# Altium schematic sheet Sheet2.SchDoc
size A3; SheetNumber: 2; SheetTotal: 2
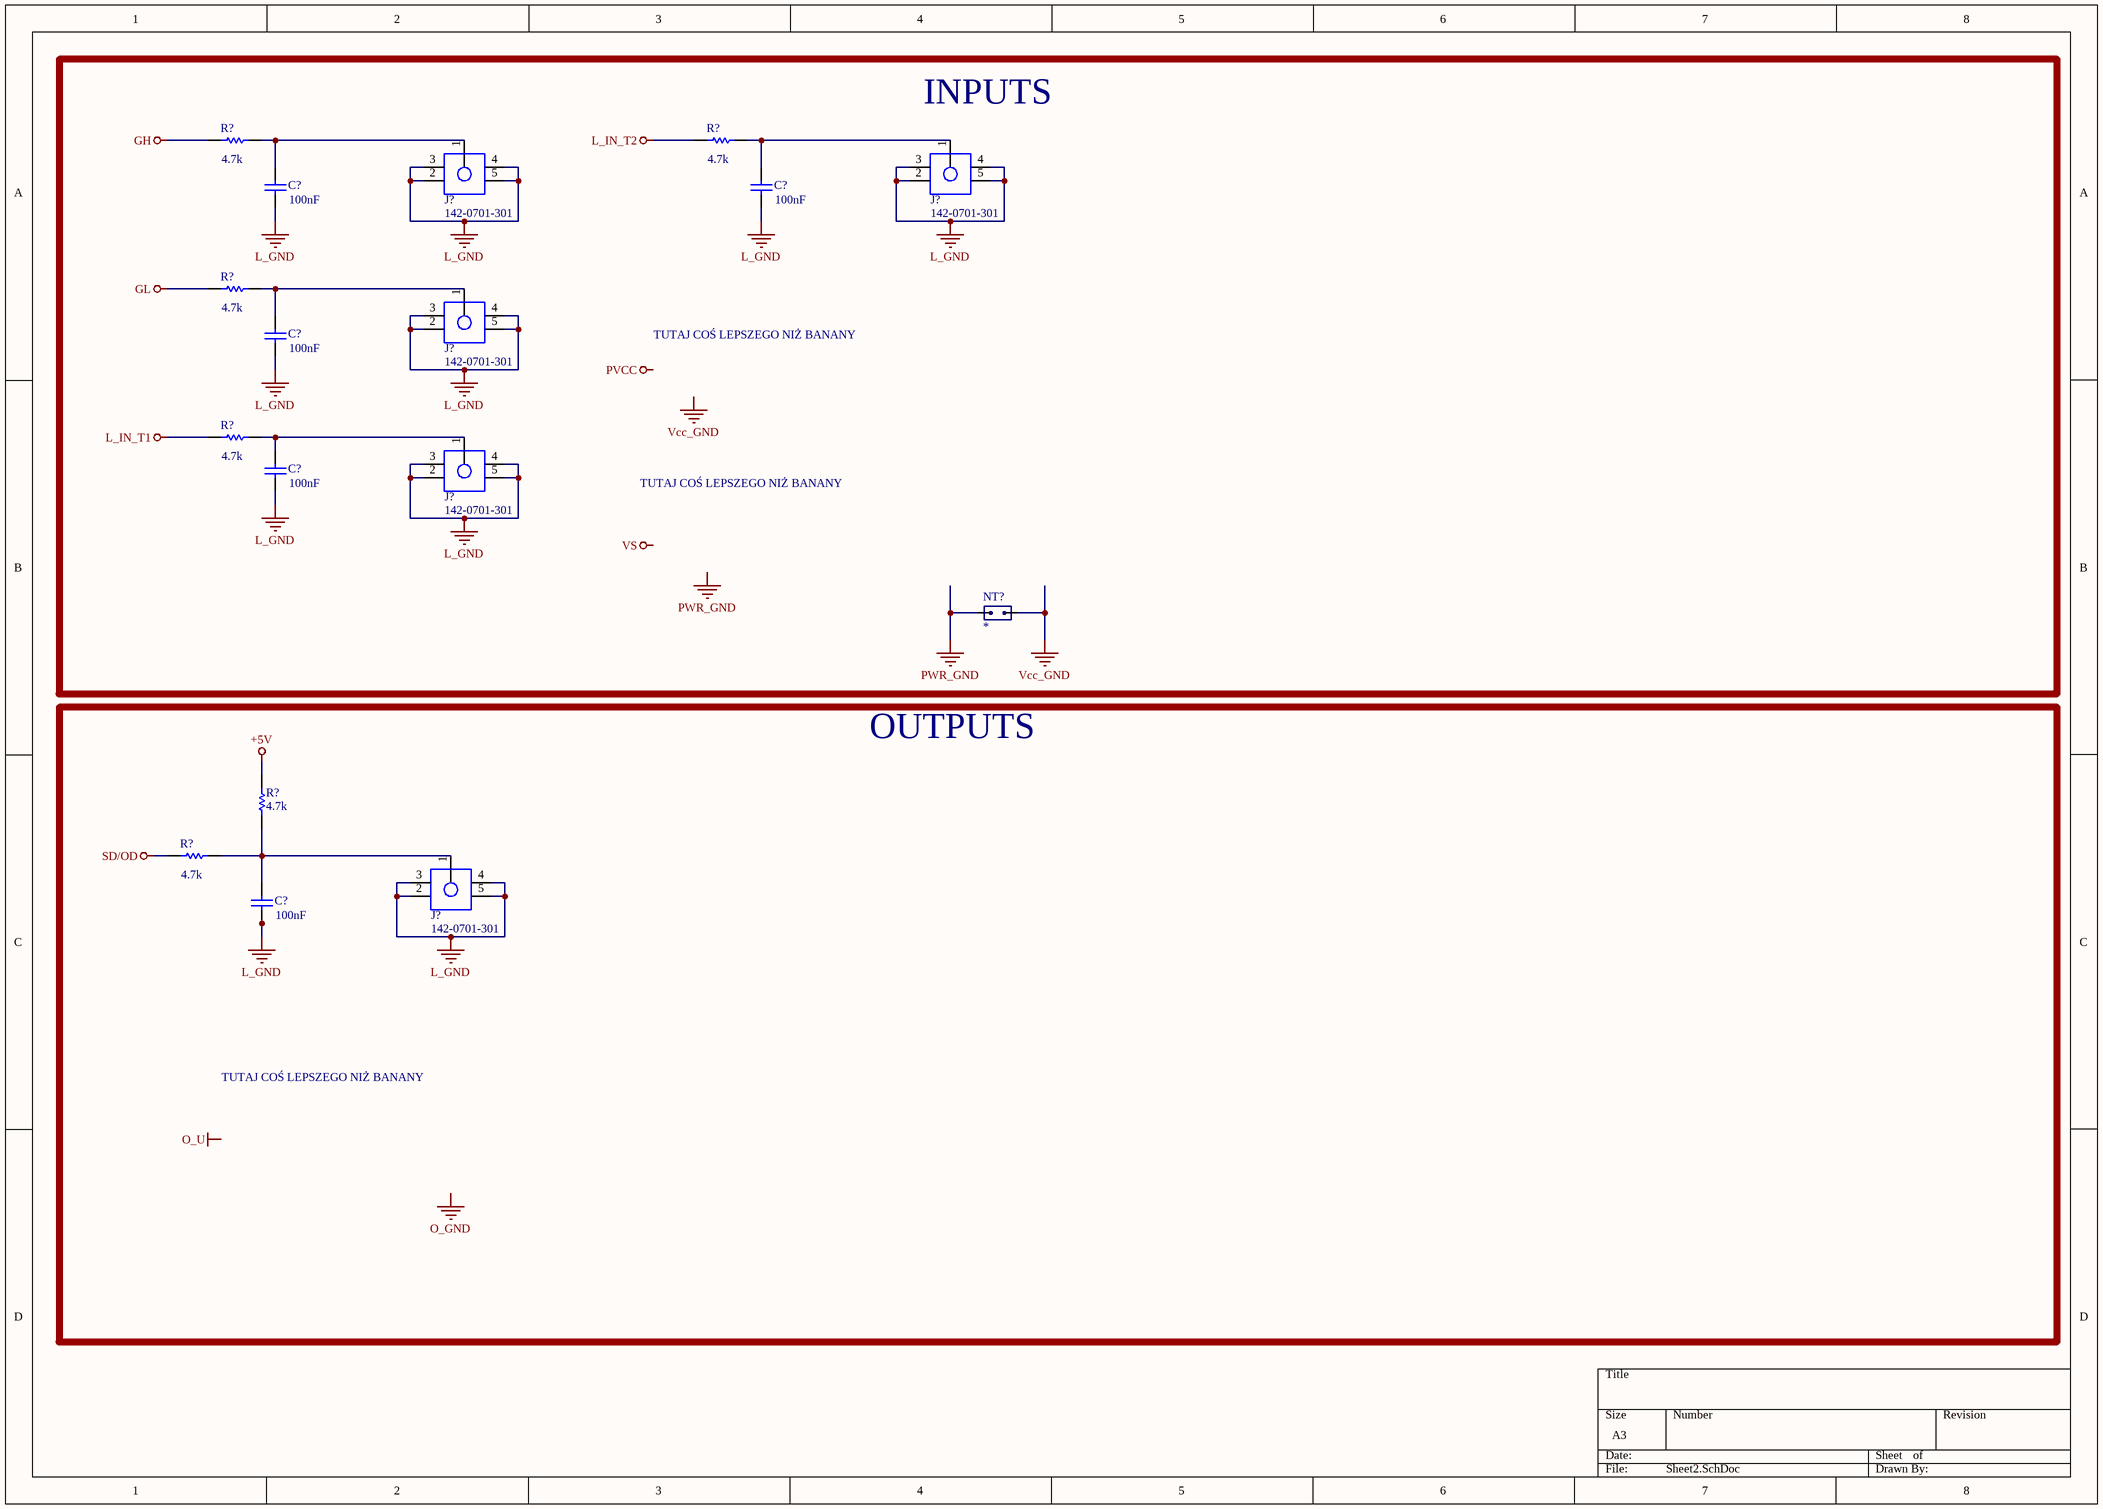
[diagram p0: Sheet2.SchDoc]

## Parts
(Parts that share a designator on the sheet are numbered #1, #2 ... from top to bottom, then left to right.)
C?#1  Capacitance: 100nF  [AVX-1206-2_L]  (hidden comment: 1206GC102KAT1A)
C?#2  Capacitance: 100nF  [AVX-1206-2_L]  (hidden comment: 1206GC102KAT1A)
C?#3  Capacitance: 100nF  [AVX-1206-2_L]  (hidden comment: 1206GC102KAT1A)
C?#4  Capacitance: 100nF  [AVX-1206-2_L]  (hidden comment: 1206GC102KAT1A)
C?#5  Capacitance: 100nF  [AVX-1206-2_L]  (hidden comment: 1206GC102KAT1A)
J?#1  142-0701-301  [1420701301]
J?#2  142-0701-301  [1420701301]
J?#3  142-0701-301  [1420701301]
J?#4  142-0701-301  [1420701301]
J?#5  142-0701-301  [1420701301]
NT?  *  [Net tie]  (net tie, no BOM)
R?#1  Resistance: 4.7k  [RESC3216X60X45ML15T20]  (hidden comment: CRCW12064K70FKEA)
R?#2  Resistance: 4.7k  [RESC3216X60X45ML15T20]  (hidden comment: CRCW12064K70FKEA)
R?#3  Resistance: 4.7k  [RESC3216X60X45ML15T20]  (hidden comment: CRCW12064K70FKEA)
R?#4  Resistance: 4.7k  [RESC3216X60X45ML15T20]  (hidden comment: CRCW12064K70FKEA)
R?#5  Resistance: 4.7k  [RESC3216X60X45ML15T20]  (hidden comment: CRCW12064K70FKEA)
R?#6  Resistance: 4.7k  [RESC3216X60X45ML15T20]  (hidden comment: CRCW12064K70FKEA)

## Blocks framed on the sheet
INPUTS: C?#1-C?#4 J?#1-J?#4 NT? R?#1-R?#4
OUTPUTS: C?#5 J?#5 R?#5 R?#6

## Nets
+5V: R?#5.2
GH: R?#1.1
GL: R?#3.1
L_GND: C?#1.1 C?#2.1 C?#3.1 C?#4.1 C?#5.1 J?#1.2 J?#1.3 J?#1.4 J?#1.5 J?#2.2 J?#2.3 J?#2.4 J?#2.5 J?#3.2 J?#3.3 J?#3.4 J?#3.5 J?#4.2 J?#4.3 J?#4.4 J?#4.5 J?#5.2 J?#5.3 J?#5.4 J?#5.5
L_IN_T1: R?#4.1
L_IN_T2: R?#2.1
PWR_GND: NT?.1
SD/OD: R?#6.1
Vcc_GND: NT?.2
NetC?#1_2: C?#1.2 J?#1.1 R?#1.2
NetC?#2_2: C?#2.2 J?#2.1 R?#2.2
NetC?#3_2: C?#3.2 J?#3.1 R?#3.2
NetC?#4_2: C?#4.2 J?#4.1 R?#4.2
NetC?#5_2: C?#5.2 J?#5.1 R?#5.1 R?#6.2

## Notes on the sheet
- TUTAJ COŚ LEPSZEGO NIŻ BANANY
- Labels drawn without touching a wire or pin: O_GND, O_U, PVCC, PWR_GND, Vcc_GND, VS

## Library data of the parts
C?#1-C?#5 = CMP-2000-05468-1: Chip Capacitor, 1 nF, +/- 10%, -55 to 125 degC, 1206 (3216 Metric), RoHS, Tape and Reel; Manufacturer: AVX; Dielectric: X7R; Voltage Rating DC: 2000V
J?#1-J?#5 = 142-0701-301: Connector; Manufacturer_Name: Cinch Connectivity Solutions
NT? = Net tie
R?#1-R?#6 = CMP-2100-03618-1: Chip Resistor, 4.7 KOhm, +/- 1%, 0.25 W, -55 to 155 degC, 1206 (3216 Metric), RoHS, Tape and Reel; Manufacturer: Vishay Semiconductor; Power Rating: 250mW; Voltage Rating: 200V; Temperature Coefficient: 100ppm/degreesC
